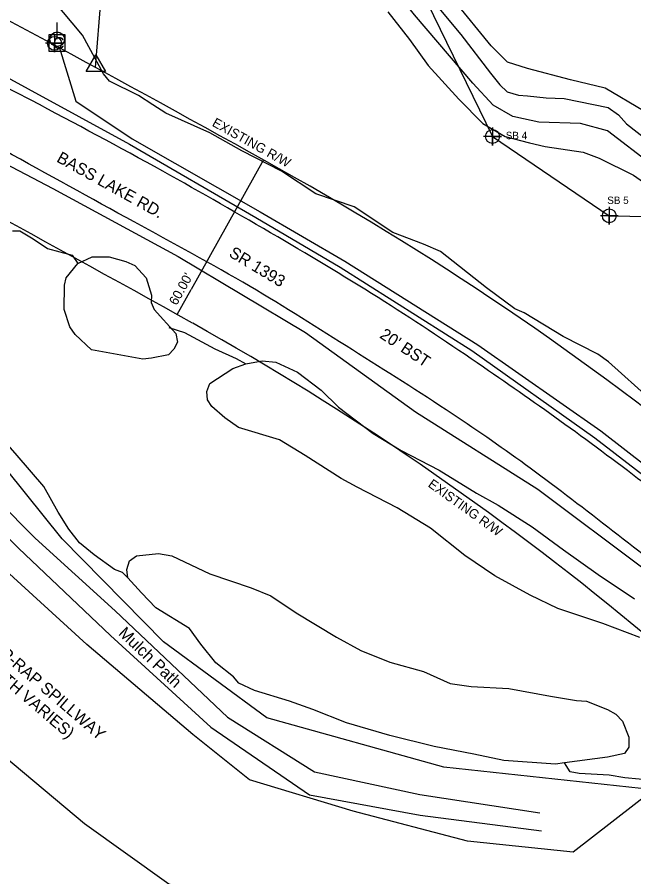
# Model space of a CAD drawing. Extents: x 2057786 to 2059508, y 687766 to 689280.
# Drawn here: x 2058495.3 to 2058704.1, y 688748.5 to 689039.8 of the extents above; entities that cross this region are included whole.
import ezdxf

# ---------------------------------------------------------------- set-up
doc = ezdxf.new("R2010")
doc.units = 0
for name, color, linetype in [('Default', 7, 'Continuous'), ('Exist Property Line', 7, 'Continuous'), ('Exist Right of Way Line', 7, 'Continuous'), ('Exist Right of Way Line Text', 7, 'Continuous'), ('Exist Right of Way Monument CELL', 7, 'Continuous'), ('Exist Right of Way Width CELL', 7, 'Continuous'), ('Exist Roads EOP', 7, 'Continuous'), ('Exist Roads EOP Text', 7, 'Continuous'), ('Exist Roads Soil', 7, 'Continuous'), ('Exist Roads Soil Text', 7, 'Continuous'), ('Exist Utilities Other Pole CELL', 7, 'Continuous'), ('Exist Utilities Power Pole CELL', 7, 'Continuous'), ('Exist Utilities Telephone UG FO', 7, 'Continuous'), ('Exist Utilities Telephone UG FO Cogo Point CELL', 7, 'Continuous'), ('Exist Utilities TV Pedestal CELL', 7, 'Continuous'), ('Old_Level_10', 7, 'Continuous'), ('Old_Level_11', 7, 'Continuous'), ('Old_Level_28', 7, 'Continuous'), ('Old_Level_8', 7, 'Continuous')]:
    doc.layers.add(name, color=color, linetype=linetype)

# ---------------------------------------------------------------- blocks, each defined once
blk = doc.blocks.new('EXIST UTILITIES TELEPHONE UG FO COGO POINT')
at = {"layer": 'Exist Utilities Telephone UG FO Cogo Point CELL'}
blk.add_lwpolyline([(0, 0.06), (0, -0.06), (0, 0), (0.06, 0), (-0.06, 0)], dxfattribs=at)
blk.add_circle((0, 0), 0.0469, dxfattribs=at)
blk = doc.blocks.new('EXIST UTILITIES POWER POLE')
at = {"layer": 'Exist Utilities Power Pole CELL'}
for q in [(0, 0.1125), (0, 0)]:
    blk.add_line((0, 0), q, dxfattribs=at)
blk.add_circle((0, 0), 0.049, dxfattribs=at)
blk = doc.blocks.new('EXIST UTILITIES TV PEDESTAL')
at = {"layer": 'Exist Utilities TV Pedestal CELL'}
blk.add_line((0, 0), (0, 0), dxfattribs=at)
blk.add_lwpolyline([(-0.0555, -0.0555), (0.0555, -0.0555), (0.0555, 0.0555), (-0.0555, 0.0555), (-0.0555, -0.0555)], dxfattribs=at)
blk.add_text('C', height=0.08, dxfattribs=at).set_placement((-0.0261, -0.04))
blk = doc.blocks.new('EXIST RIGHT OF WAY MONUMENT')
at = {"layer": 'Exist Right of Way Monument CELL'}
blk.add_line((0, 0), (0, 0), dxfattribs=at)
blk.add_lwpolyline([(-0.065, -0.0378), (0, 0.075), (0.065, -0.0378)], close=True, dxfattribs=at)
blk = doc.blocks.new('EXIST UTILITIES OTHER POLE')
at = {"layer": 'Exist Utilities Other Pole CELL'}
blk.add_circle((0, 0), 0.0493, dxfattribs=at)

msp = doc.modelspace()

# ---------------------------------------------------------------- linework, layer by layer
at = {"layer": 'Default'}
for points in [[(2058577.72, 689095.69), (2058593.95, 689087.58), (2058629.6, 689054.14), (2058656.28, 688999.33), (2058695.83, 688972.46), (2058723.84, 688971.95), (2058746.31, 688965.24), (2058769.31, 688973.27), (2058806.85, 688970.66), (2058846.21, 688963.3)], [(2058656.28, 689002.33), (2058656.28, 688996.33), (2058656.28, 688999.33), (2058659.28, 688999.33), (2058653.28, 688999.33)], [(2058695.83, 688975.46), (2058695.83, 688969.46), (2058695.83, 688972.46), (2058698.83, 688972.46), (2058692.83, 688972.46)]]:
    msp.add_lwpolyline(points, dxfattribs=at)
for centre in [(2058656.28, 688999.33), (2058695.83, 688972.46)]:
    msp.add_circle(centre, 2.34, dxfattribs=at)
at = {"layer": 'Exist Property Line'}
msp.add_line((2058521.86, 689022.72), (2058533.17, 689165.21), dxfattribs=at)
at = {"layer": 'Exist Right of Way Line'}
msp.add_line((2058713.24, 688826.13), (2058704.14, 688833.67), dxfattribs=at)
for centre, radius, start, end in [((2055622.73, 683696.35), 6064.25, 60.769843, 62.505867), ((2055622.73, 683696.35), 6004.25, 60.769843, 62.505867), ((2058065.77, 688062.25), 1061.3, 50.39101, 60.76984), ((2058065.77, 688062.25), 1001.3, 50.39101, 60.76984)]:
    msp.add_arc(centre, radius, start, end, dxfattribs=at)
at = {"layer": 'Exist Right of Way Width CELL'}
for p in [(2058578.69, 688991.39), (2058549.44, 688939)]:
    msp.add_line(p, (2058554.16, 688947.45), dxfattribs=at)
at = {"layer": 'Exist Roads EOP'}
msp.add_lwpolyline([(2058500.05, 689011.62), (2058489.26, 689017.05), (2058484.73, 689021.35), (2058455.29, 689037.52), (2058440.84, 689043.12), (2058407.76, 689060.49), (2058364.53, 689082.85), (2058318.19, 689106.92), (2058272.72, 689130.83), (2058226.89, 689154.25)], dxfattribs=at)
for points in [[(2058807.54, 688798.57), (2058788.55, 688814.04), (2058763.66, 688835.8), (2058737.1, 688858.45), (2058708.93, 688880.81), (2058680.81, 688901.78), (2058653.18, 688921.17), (2058619.8, 688943.33), (2058583.53, 688965.28), (2058544.59, 688987.58), (2058500.05, 689011.62)], [(2058790.44, 688783.33), (2058774.52, 688799.91), (2058750.56, 688821.57), (2058724.88, 688843.53), (2058697.06, 688865.63), (2058669.08, 688886.89), (2058642.64, 688905.34), (2058608.82, 688927.02), (2058574.14, 688948.51), (2058534.92, 688970.39), (2058490.85, 688994.7)]]:
    msp.add_spline(points, degree=3, dxfattribs=at)
at = {"layer": 'Exist Roads Soil'}
for points in [[(2058392.23, 688962.26), (2058403.46, 688949.91), (2058436.05, 688924.4), (2058463.33, 688901.57), (2058501.42, 688863.21), (2058528.5, 688838.55), (2058566.54, 688802.58), (2058595.96, 688784), (2058631.65, 688776.32), (2058672.35, 688770.1)], [(2058381.8, 688957.42), (2058398.21, 688943), (2058431.63, 688918.41), (2058461.61, 688893.72), (2058495.76, 688859.78), (2058526.85, 688830.27), (2058560.88, 688799.23), (2058594.24, 688776.2), (2058631.79, 688769.37), (2058672.86, 688764.1)]]:
    msp.add_lwpolyline(points, dxfattribs=at)
at = {"layer": 'Exist Utilities Telephone UG FO'}
for points in [[(2058380.13, 689037.88), (2058409.05, 689027.45), (2058445.6, 689009.54), (2058463.36, 689004.77), (2058507.34, 688981.72), (2058549.85, 688958.72), (2058592.91, 688932.87), (2058630.21, 688906.05), (2058671.59, 688879.88), (2058708.13, 688852.45), (2058716.78, 688839.32), (2058719.03, 688829.69)], [(2058509.48, 689029.69), (2058515.11, 689011.34), (2058534.24, 688998.53), (2058577.62, 688973.82), (2058606.21, 688957.1), (2058651.27, 688928.78), (2058692.96, 688899.56), (2058733.89, 688867.9), (2058766.96, 688840.32), (2058800.79, 688815.54)], [(2058481.78, 689024.87), (2058533.28, 688996.69), (2058576.13, 688971.91), (2058604.64, 688955.03), (2058649.28, 688926.77), (2058690.89, 688897.21), (2058732.29, 688865.4), (2058765.01, 688837.78), (2058802.11, 688813.98)]]:
    msp.add_lwpolyline(points, dxfattribs=at)
at = {"layer": 'Old_Level_10'}
for points in [[(2058800.95, 688974.23), (2058791.12, 688975.22), (2058776.66, 688972.48), (2058749.15, 688970.56), (2058739.7, 688970.17), (2058731.03, 688972.98), (2058710.26, 688989.76), (2058695.18, 689001.26), (2058686.08, 689003.69), (2058672.01, 689004.17), (2058666.8, 689005.27), (2058663.19, 689006.08), (2058656.51, 689009.9), (2058649.63, 689017.38), (2058629.83, 689040.6), (2058607.74, 689068.1), (2058600.81, 689080.36), (2058592.68, 689101.92)], [(2058627.83, 689055.29), (2058645.6, 689033.91), (2058655.62, 689020.77), (2058658.74, 689016.84), (2058661.25, 689014.47), (2058665.14, 689013.34), (2058668.17, 689013.17), (2058674.42, 689012.42), (2058680.59, 689012.18), (2058695.44, 689009.12), (2058698.95, 689006.69), (2058701.72, 689003.59), (2058712.51, 688995.18), (2058729.25, 688982.48), (2058732.27, 688980.18), (2058735.03, 688978.81), (2058743.11, 688976.86), (2058756.52, 688978.86), (2058780.36, 688982.3), (2058789.7, 688982.39), (2058800.77, 688982.48)]]:
    msp.add_lwpolyline(points, dxfattribs=at)
at = {"layer": 'Old_Level_11'}
for points in [[(2058797.73, 688989.54), (2058784.77, 688989.66), (2058775.21, 688988.97), (2058768.6, 688988.43), (2058756.79, 688987.27), (2058741.66, 688986.59), (2058738.54, 688986.87), (2058728.71, 688990.35), (2058722.42, 688993.74), (2058713.52, 689002.84), (2058707.45, 689008.04), (2058694.49, 689015.71), (2058682.69, 689018.58), (2058668.15, 689022.42), (2058661.34, 689024.47), (2058655.87, 689030.06), (2058643.29, 689045.44), (2058626.17, 689066.54), (2058614.99, 689079.84), (2058610.73, 689085.15), (2058606.21, 689094.42), (2058599.92, 689111.87)], [(2058709.96, 688910.09), (2058695.54, 688923.01), (2058691.94, 688925.53), (2058680.26, 688931.53), (2058666.98, 688939.54), (2058663.82, 688940.93), (2058654.23, 688948.03), (2058638.66, 688960.31), (2058632.94, 688962.85), (2058622.47, 688966.86), (2058609.42, 688975.46), (2058596.44, 688979.92), (2058584.76, 688987.64), (2058571.41, 688994.44), (2058560.55, 689000.6), (2058545.58, 689007.29), (2058541.19, 689010.05), (2058536.42, 689013.24), (2058526.5, 689018.13), (2058524.52, 689020.56), (2058517.38, 689033.68), (2058507.45, 689045.63)], [(2058620.85, 689041.61), (2058628.11, 689032.22), (2058634.48, 689023.37), (2058644.86, 689011.98), (2058652.98, 689003.75), (2058660.61, 688999.28), (2058668.78, 688997.21), (2058674.16, 688995.9), (2058686.99, 688993.98), (2058692.43, 688991.96), (2058704.04, 688986.26), (2058712.3, 688980.44), (2058715.85, 688977.11), (2058721.22, 688973.68), (2058725.25, 688969.82), (2058727.28, 688968.19), (2058736.37, 688964.46), (2058747.58, 688960.51), (2058758.26, 688959.53), (2058767.36, 688959.24), (2058781.2, 688962.22), (2058795.31, 688964.67), (2058798.39, 688965.31), (2058806.3, 688963.75)], [(2058493.72, 688967.38), (2058496.23, 688967.34), (2058500.72, 688964.67), (2058505.57, 688961.38), (2058513.88, 688959.09), (2058515.82, 688956.29)], [(2058532.81, 688849.75), (2058531, 688851.57), (2058528.26, 688852.55), (2058521.3, 688857.59), (2058516.39, 688861.6), (2058512.82, 688866.23), (2058509.12, 688872.08), (2058504.26, 688880.72), (2058495.27, 688891.2), (2058485.13, 688902.75), (2058476.37, 688911.9), (2058464.41, 688919.73), (2058461.58, 688921.4), (2058455.02, 688928.31), (2058446.29, 688938.07), (2058436.58, 688946.55), (2058428.75, 688954.61), (2058425.15, 688958.63), (2058424.1, 688961.31), (2058424.79, 688964.06)], [(2058520.43, 688927.05), (2058514.88, 688932.2), (2058513.11, 688934.81), (2058511.23, 688940.75), (2058511.29, 688949), (2058511.92, 688951.47), (2058515.82, 688956.29), (2058520.68, 688958.55), (2058526.43, 688958.54), (2058532.08, 688956.92), (2058535.13, 688955.64), (2058538.93, 688951.4), (2058540.73, 688945.57), (2058540.69, 688943.07), (2058541.67, 688940.7), (2058548.98, 688932.53), (2058549.63, 688929.67), (2058548.38, 688927.22), (2058546.57, 688925.4), (2058540.75, 688924.21), (2058537.81, 688923.87), (2058520.43, 688927.05)], [(2058546.64, 688934.64), (2058551.93, 688932.87), (2058562.21, 688927.35), (2058569.46, 688924.08), (2058572.69, 688922.3)], [(2058706.13, 688829.55), (2058693.69, 688834.27), (2058678.45, 688839.36), (2058669.02, 688843.92), (2058657.08, 688850.43), (2058646.88, 688857.35), (2058635.3, 688866.66), (2058624, 688873.54), (2058610.48, 688880.55), (2058604.99, 688883.47), (2058592.82, 688891.29), (2058584.15, 688896.51), (2058570.28, 688900.7), (2058565.62, 688903.97), (2058561.2, 688907.83), (2058559.72, 688910.13), (2058559.47, 688912.96), (2058560.53, 688915.63), (2058568.37, 688920.73), (2058572.69, 688922.3), (2058578.28, 688923.3), (2058582.89, 688922.85), (2058590.26, 688919.52), (2058598.29, 688913.34), (2058604.12, 688907.67), (2058615.81, 688898.66), (2058625.36, 688892.88), (2058638.18, 688886.21), (2058650.83, 688878.44), (2058658.25, 688874.39), (2058669.72, 688867.11), (2058680.35, 688859.26), (2058692.06, 688850.86), (2058704.38, 688842.62)], [(2058562.58, 688820.93), (2058557.5, 688827.25), (2058553.68, 688832.6), (2058542.2, 688839.67), (2058537.35, 688844.67), (2058532.81, 688849.75), (2058532.37, 688852.59), (2058533.34, 688855.56), (2058535.64, 688857.24), (2058543.13, 688858.03), (2058547.62, 688857.28), (2058560.55, 688851.12), (2058574.59, 688846.34), (2058581.19, 688843.66), (2058589.73, 688837.95), (2058603.47, 688829.63), (2058611.68, 688825.14), (2058621.53, 688821.17), (2058632.93, 688818.02), (2058641.89, 688814.02), (2058649, 688812.93), (2058661.76, 688812.3), (2058675.92, 688809.68), (2058684.71, 688808.19), (2058688.12, 688808), (2058695.24, 688805.21), (2058698.07, 688803.54), (2058700.36, 688801.19), (2058702.49, 688795.83), (2058702.5, 688792.4), (2058700.97, 688790.27), (2058695.25, 688788.97), (2058680.71, 688787.06), (2058677.66, 688786.63), (2058660.08, 688787.9), (2058649.91, 688790.08), (2058636.55, 688792.64), (2058621.53, 688796.4), (2058606.85, 688800.64), (2058595.41, 688805.11), (2058587.51, 688807.97), (2058575.71, 688811.55), (2058570.41, 688814.06), (2058568.51, 688816.18), (2058562.58, 688820.93)], [(2058715.62, 688780.67), (2058701.05, 688781.98), (2058695.85, 688782.88), (2058685.59, 688783.44), (2058682.59, 688784.01), (2058680.71, 688787.06)]]:
    msp.add_lwpolyline(points, dxfattribs=at)
at = {"layer": 'Old_Level_8'}
for points in [[(2058710.76, 688777.94), (2058639.82, 688785.6), (2058579.89, 688802.35), (2058544.82, 688828.11), (2058510.55, 688863.02), (2058485.54, 688893.98), (2058454.38, 688921.53), (2058422.23, 688952.56), (2058403.03, 688979.97)], [(2058734.92, 688753.52), (2058735.51, 688760.64), (2058736.99, 688765.98), (2058740.85, 688771.33), (2058730.47, 688774.89), (2058710.76, 688777.94), (2058683.64, 688756.81), (2058647.8, 688760.5), (2058609.04, 688770.73), (2058573.94, 688781.35), (2058554.73, 688796.64), (2058518.83, 688827.17), (2058480.84, 688861.92), (2058432.5, 688905.71), (2058398.97, 688932.94), (2058365.98, 688953.37), (2058338.05, 688966.46), (2058319.19, 688970.72), (2058307.26, 688971.08), (2058292.32, 688971.2)], [(2058243.89, 688914.56), (2058274.94, 688919.33), (2058297.8, 688918.3), (2058350.46, 688908.85), (2058379.27, 688886.03), (2058459.18, 688815.88), (2058518.04, 688766.49), (2058546.6, 688746.07), (2058577.46, 688734.39), (2058606.33, 688729.69), (2058618.83, 688725.97), (2058623.23, 688723.41), (2058623.36, 688718.56), (2058621.09, 688706.79), (2058622.32, 688699.87), (2058624.31, 688695.72), (2058627.84, 688693.91), (2058629.3, 688692.92), (2058633.15, 688691.6), (2058635.7, 688693.01)]]:
    msp.add_lwpolyline(points, dxfattribs=at)

# ---------------------------------------------------------------- block references
at = {"layer": 'Exist Right of Way Monument CELL', "xscale": 50, "yscale": 50}
msp.add_blockref('EXIST RIGHT OF WAY MONUMENT', (2058521.91, 689023.3), dxfattribs=at)
at = {"layer": 'Exist Utilities Other Pole CELL', "xscale": 50, "yscale": 50}
msp.add_blockref('EXIST UTILITIES OTHER POLE', (2058508.82, 689032.29), dxfattribs=at)
at = {"layer": 'Exist Utilities Power Pole CELL', "xscale": 50, "yscale": 50}
msp.add_blockref('EXIST UTILITIES POWER POLE', (2058508.82, 689032.29), dxfattribs=at)
at = {"layer": 'Exist Utilities Telephone UG FO Cogo Point CELL', "xscale": 50, "yscale": 50}
msp.add_blockref('EXIST UTILITIES TELEPHONE UG FO COGO POINT', (2058507.92, 689030.91), dxfattribs=at)
at = {"layer": 'Exist Utilities TV Pedestal CELL', "xscale": 50, "yscale": 50}
msp.add_blockref('EXIST UTILITIES TV PEDESTAL', (2058508.73, 689031.01), dxfattribs=at)

# ---------------------------------------------------------------- texts
at = {"layer": 'Default'}
for s, p in [('SB 4', (2058660.77, 688998.43)), ('SB 5', (2058695.15, 688976.47))]:
    msp.add_text(s, height=2.5, dxfattribs=at).set_placement(p)
at = {"layer": 'Exist Right of Way Line Text'}
for rotation, p in [(330.8766, (2058561.04, 689003.06)), (324.3124, (2058634.18, 688880.89))]:
    msp.add_text('EXISTING R/W', height=3.2, rotation=rotation, dxfattribs=at).set_placement(p)
at = {"layer": 'Exist Right of Way Width CELL'}
msp.add_text("60.00'", height=3.2, rotation=60.8276, dxfattribs=at).set_placement((2058549.3, 688941.88))
at = {"layer": 'Exist Roads EOP Text'}
for s, rotation, p in [('BASS LAKE RD.', 330.9687, (2058508.34, 688990.95)), ('SR 1393', 328.93, (2058566.69, 688958.87)), ("20' BST", 326.697, (2058617.76, 688931.31))]:
    msp.add_text(s, height=4, rotation=rotation, dxfattribs=at).set_placement(p)
at = {"layer": 'Exist Roads Soil Text'}
msp.add_text('Mulch Path', height=4, rotation=316.4926, dxfattribs=at).set_placement((2058529.29, 688830.64))
at = {"layer": 'Old_Level_28'}
for s, p in [('RIP-RAP SPILLWAY', (2058485.15, 688826.99)), ('(WIDTH VARIES)', (2058480.51, 688822.51))]:
    msp.add_text(s, height=4, rotation=319.3747, dxfattribs=at).set_placement(p)

doc.saveas('drawing.dxf')
